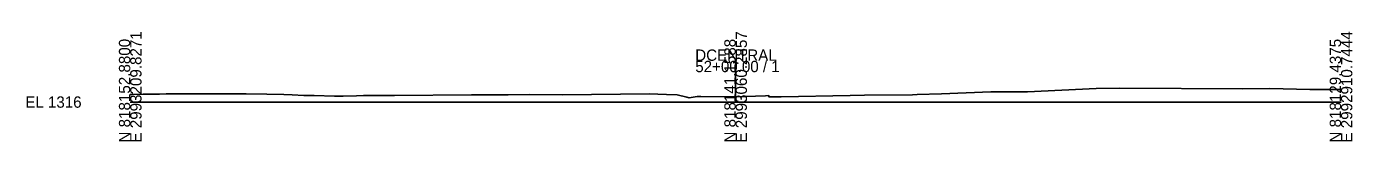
# Model space of a CAD drawing. Extents: x 124 to 2053, y -55 to 2017.
# Drawn here: x 124.3 to 452.8, y 1990.3 to 2017.4 of the extents above; entities that cross this region are included whole.
import ezdxf

# ---------------------------------------------------------------- set-up
doc = ezdxf.new("R2010")
doc.units = 0
doc.layers.add('DESIGN - SHEET - Light Grid', color=7, linetype='Continuous')
doc.layers.add('SURVEY - GROUND - Top of Ground', color=7, linetype='Continuous')

msp = doc.modelspace()

# ---------------------------------------------------------------- linework, layer by layer
at = {"layer": 'DESIGN - SHEET - Light Grid'}
for p, q in [((300, 2000), (300, 2010.18)), ((150, 2000), (300, 2000)), ((300, 2000), (450, 2000))]:
    msp.add_line(p, q, dxfattribs=at)
at = {"layer": 'SURVEY - GROUND - Top of Ground'}
msp.add_lwpolyline([(150, 2001.87), (150.39, 2001.87), (153.2, 2001.97), (153.81, 2001.97), (155.25, 2001.97), (157.23, 2001.96), (158.87, 2001.99), (160.07, 2002.01), (161.47, 2002.04), (169.63, 2002.03), (170.93, 2002.06), (172.62, 2002.06), (173.52, 2002.06), (175.78, 2002.06), (177.32, 2002.01), (178.24, 2002), (178.73, 2002.02), (183.86, 2001.98), (188.08, 2001.88), (190.11, 2001.79), (193.05, 2001.64), (195.2, 2001.6), (195.58, 2001.59), (200.6, 2001.46), (202.77, 2001.45), (206.08, 2001.5), (207.84, 2001.61), (215.45, 2001.62), (234.53, 2001.81), (240.82, 2001.81), (242.19, 2001.77), (243.65, 2001.79), (248.97, 2001.86), (257.23, 2001.79), (278.57, 2001.99), (282.91, 2001.85), (285.49, 2001.8), (287.89, 2001.19), (288.49, 2001.05), (289.46, 2001.18), (290.5, 2001.35), (290.94, 2001.41), (291.38, 2001.41), (299.55, 2001.3), (300, 2001.31), (307.44, 2001.55), (308.24, 2001.59), (308.25, 2001.28), (311.26, 2001.31), (328.41, 2001.63), (331.92, 2001.7), (343.8, 2001.78), (345.01, 2001.84), (350.98, 2002), (363.23, 2002.51), (367.2, 2002.52), (372.36, 2002.55), (389.34, 2003.37), (395.18, 2003.39), (425.7, 2003.29), (432.39, 2003.36), (442.24, 2003.09), (443.83, 2003.09), (444.94, 2003.08), (450, 2003.12)], dxfattribs=at)

# ---------------------------------------------------------------- texts
at = {"layer": 'DESIGN - SHEET - Light Grid'}
for s, p in [('E 2993209.8271', (152.8, 1990)), ('E 2993060.2857', (302.8, 1990)), ('E 2992910.7444', (452.8, 1990)), ('N 818152.8800', (150, 1990)), ('N 818141.1588', (300, 1990)), ('N 818129.4375', (450, 1990))]:
    msp.add_text(s, height=2.8, rotation=90, dxfattribs=at).set_placement(p)
for s, p in [('DCENTRAL', (290, 2010.18)), ('52+00.00 / 1', (290, 2007.38)), ('EL 1316', (124, 1998.6))]:
    msp.add_text(s, height=2.8, dxfattribs=at).set_placement(p)

doc.saveas('drawing.dxf')
